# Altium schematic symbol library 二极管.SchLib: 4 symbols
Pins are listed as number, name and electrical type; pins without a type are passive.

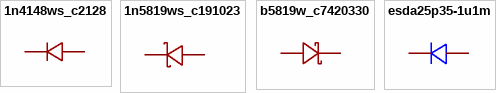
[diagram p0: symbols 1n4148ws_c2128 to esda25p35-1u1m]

## 1n4148ws_c2128
designator D??  (value not drawn)
二极管配置:独立式;整流电流:150mA;直流反向耐压(Vr):100V;正向压降(Vf):1.25V@150mA;反向恢复时间(Trr):4ns;; Manufacturer: CJ(江苏长电/长晶); Symbol: 1N4148WS T4; AddInBom: yes; ModelId: db63db13d9e342eb939127d413d6200b; ModelName: SOD-323_L1.8-W1.3-LS2.5-RD; ModelTransform: 104.3305,51.181,0,0,0,0,0,-0.004,0; Diode Configuration: 独立式; Pd - Power Dissipation: 200mW; Current - Rectified: 150mA; Voltage - DC Reverse(Vr): 100V; Non-Repetitive Peak Forward Surge Current: 2A; Reverse Leakage Current (Ir): 1uA@75V; Reverse Recovery Time (trr): 4ns
footprint SOD-323_L1.8-W1.3-LS2.5-RD
pins: 1 K, 2 A

## 1n5819ws_c191023
designator D??  (value not drawn)
正向压降(Vf):600mV@1A;直流反向耐压(Vr):40V;整流电流:1A;; Manufacturer: Hottech(合科泰); AddInBom: yes; ModelId: db63db13d9e342eb939127d413d6200b; ModelName: SOD-323_L1.8-W1.3-LS2.5-RD; ModelTransform: 104.3305,51.181,0,0,0,0,0,-0.004,0; Voltage - DC Reverse(Vr): 40V; Current - Rectified: 1A; Non-Repetitive Peak Forward Surge Current: 25A
footprint SOD-323_L1.8-W1.3-LS2.5-RD
footprint SOD-323_L1.8-W1.3-LS2.5-RD (Footprint not found)
pins: 1 K, 2 A

## b5819w_c7420330
designator D??  (value not drawn)
二极管配置:独立式;正向压降(Vf):600mV@1.0A;直流反向耐压(Vr):40V;整流电流:1A;; Manufacturer: R+O(宏嘉诚); ManufacturerPart: B5819W; AddInBom: yes; ModelId: 5054d9b7be8b429dad093a54b517b4dd; ModelName: SOD-123_L2.7-W1.6-LS3.7-FD; ModelTransform: 145.669,61.024,0,0,0,0,0,0,0; Diode Configuration: 独立式; Voltage - DC Reverse(Vr): 40V; Current - Rectified: 1A; Reverse Leakage Current (Ir): 1mA@30V; Operating Junction Temperature Range: -55℃~+150℃; Non-Repetitive Peak Forward Surge Current: 9A
footprint SOD-123_L2.7-W1.6-LS3.7-FD
pins: 1 A, 2 K

## esda25p35-1u1m
designator D??  (value not drawn)
极性:单向;反向截止电压(Vrwm):22V;钳位电压:41V;峰值脉冲电流(Ipp):35A@8/20us;峰值脉冲功率(Ppp):1.4kW@8/20us;击穿电压(VBR):24.6V;; Manufacturer: ST(意法半导体); AddInBom: yes; ModelId: bee06c9344af42398f6dfc46bef07411; ModelName: DFN1610-2_L1.6-W1.0-P1.05-RD; ModelTransform: 62.992,39.37,0,0,0,0,0,0,0; Polarity: 单向; Reverse Stand-Off Voltage (Vrwm): 22V; Clamping Voltage: 41V; Voltage - Breakdown: 24.6V; Reverse Leakage Current (Ir): 200nA; Number of Channels: 单路; level of protection: IEC 61000-4-2; Type: TVS
footprint DFN1610-2_L1.6-W1.0-P1.05-RD
pins: 1, 2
